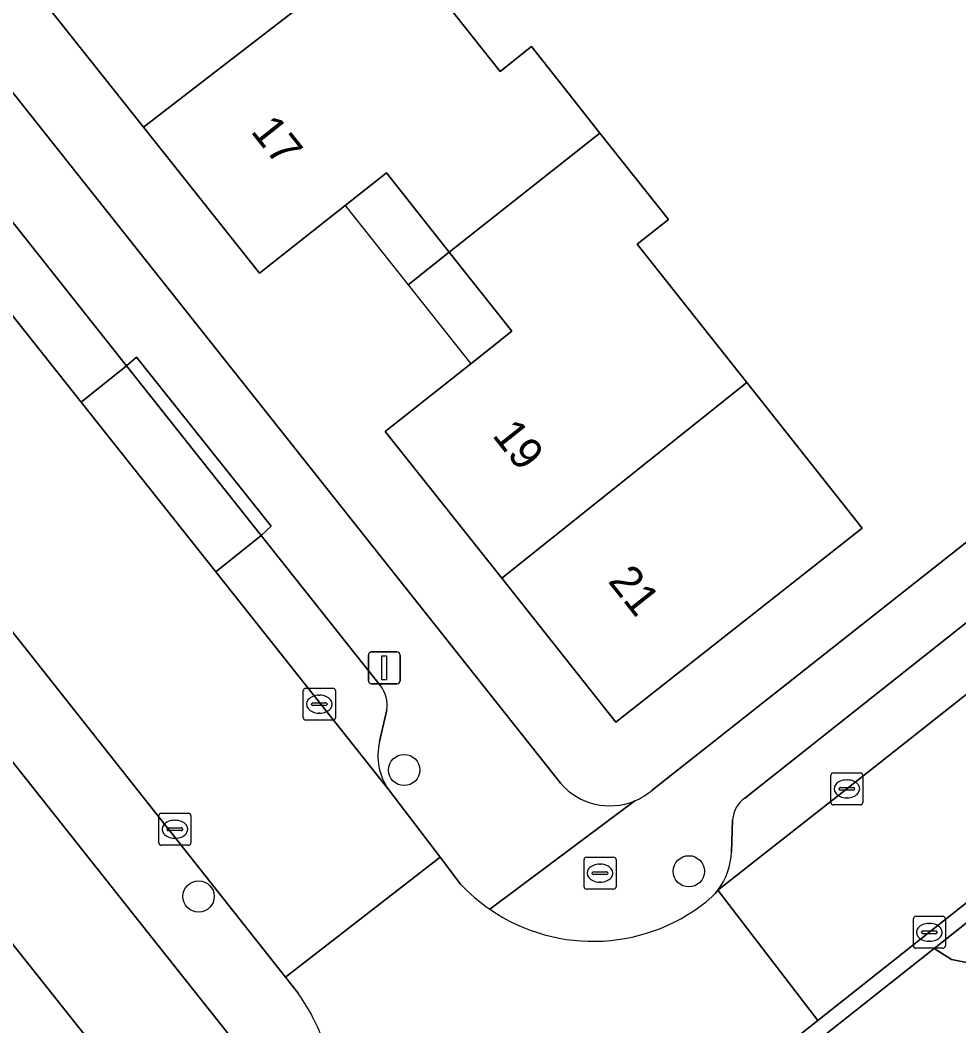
# Model space of a CAD drawing. Extents: x 159626 to 160723, y 388173 to 389416.
# Drawn here: x 160154.71 to 160184.07, y 388555.62 to 388587.08 of the extents above; entities that cross this region are included whole.
import ezdxf

# ---------------------------------------------------------------- set-up
doc = ezdxf.new("R2010")
doc.units = 0
for name, color, linetype in [('IMGEO_Boom', 7, 'Continuous'), ('IMGEO_Brandkraan', 7, 'Continuous'), ('IMGEO_Erf', 7, 'Continuous'), ('IMGEO_Groenvoorziening', 7, 'Continuous'), ('IMGEO_Kolk', 7, 'Continuous'), ('IMGEO_Lichtmast', 7, 'Continuous'), ('IMGEO_Muur', 7, 'Continuous'), ('IMGEO_Pand', 7, 'Continuous'), ('IMGEO_Pand_nummerreeks', 7, 'Continuous'), ('IMGEO_Pand_overbouw', 7, 'Continuous'), ('IMGEO_Parkeervlak_open', 7, 'Continuous'), ('IMGEO_Rijbaan_lokaal_open', 7, 'Continuous'), ('IMGEO_Voetpad_halfverhard', 7, 'Continuous'), ('IMGEO_Voetpad_open', 7, 'Continuous')]:
    doc.layers.add(name, color=color, linetype=linetype)

msp = doc.modelspace()

# ---------------------------------------------------------------- linework, layer by layer
at = {"layer": 'IMGEO_Boom'}
for centre in [(160166.722, 388563.624), (160175.626, 388560.456), (160160.295, 388559.671)]:
    msp.add_circle(centre, 0.489, dxfattribs=at)
at = {"layer": 'IMGEO_Brandkraan'}
for p, q in [((160172.347, 388559.972), (160172.347, 388560.824)), ((160172.422, 388560.898), (160173.274, 388560.898)), ((160173.348, 388560.824), (160173.348, 388559.972)), ((160172.606, 388560.392), (160172.606, 388560.404)), ((160172.649, 388560.441), (160173.047, 388560.441)), ((160172.835, 388560.678), (160172.86, 388560.678)), ((160173.09, 388560.404), (160173.09, 388560.392)), ((160173.044, 388560.355), (160172.646, 388560.355)), ((160172.858, 388560.118), (160172.833, 388560.118)), ((160173.274, 388559.898), (160172.422, 388559.898))]:
    msp.add_line(p, q, dxfattribs=at)
for points in [[(160172.347, 388559.972), (160172.347, 388560.824)], [(160172.422, 388560.898), (160173.274, 388560.898)], [(160173.348, 388560.824), (160173.348, 388559.972)], [(160173.274, 388559.898), (160172.422, 388559.898)]]:
    msp.add_lwpolyline(points, dxfattribs=at)
for centre, radius, start, end in [((160172.424, 388560.822), 0.0765, 91.552, 178.448), ((160172.424, 388560.822), 0.0765, 91.552, 178.448), ((160173.272, 388560.822), 0.0765, 1.552, 88.448), ((160173.272, 388560.822), 0.0765, 1.552, 88.448), ((160172.646, 388560.401), 0.0403, 85.8775, 175.7526), ((160172.643, 388560.391), 0.0366, 178.938, 274.7102), ((160173.047, 388560.398), 0.043, 264.8664, 352.4533), ((160173.051, 388560.403), 0.0386, 1.7309, 96.639), ((160172.424, 388559.974), 0.0765, 181.552, 268.448), ((160172.424, 388559.974), 0.0765, 181.552, 268.448), ((160173.272, 388559.974), 0.0765, 271.552, 358.448), ((160173.272, 388559.974), 0.0765, 271.552, 358.448)]:
    msp.add_arc(centre, radius, start, end, dxfattribs=at)
for centre, major_axis, ratio, start_param, end_param in [((160172.834, 388560.398), (-0.387, 0.002), 0.722429, 4.712389, 7.853982), ((160172.859, 388560.398), (-0.39, 0.002), 0.717154, 1.570796, 4.712389)]:
    msp.add_ellipse(centre, major_axis=major_axis, ratio=ratio, start_param=start_param, end_param=end_param, dxfattribs=at)
at = {"layer": 'IMGEO_Erf'}
for points in [[(160135.461, 388608.789), (160171.618, 388563.205)], [(160166.344, 388589.738), (160169.723, 388585.473), (160170.703, 388586.25), (160171.884, 388584.76), (160172.846, 388583.546), (160174.989, 388580.841), (160174.009, 388580.065), (160177.437, 388575.739), (160181.04, 388571.192), (160173.345, 388565.125), (160169.775, 388569.625), (160166.133, 388574.215), (160168.803, 388576.33), (160170.09, 388577.349), (160168.135, 388579.818), (160166.17, 388582.299), (160164.883, 388581.28), (160162.203, 388579.158), (160158.576, 388583.727), (160154.932, 388588.317)], [(160174.477, 388562.996), (160194.791, 388579.03)], [(160161.479, 388555.046), (160158.23, 388559.144), (160145.158, 388575.629), (160140.484, 388571.932), (160144.027, 388567.471), (160141.577, 388565.524), (160139.117, 388563.569), (160135.574, 388568.03), (160132.045, 388565.227), (160135.588, 388560.766), (160133.044, 388558.742), (160130.663, 388556.847), (160127.12, 388561.308), (160123.577, 388558.488), (160126.051, 388555.373), (160123.516, 388553.364)], [(160142.84, 388555.036), (160147.124, 388558.426), (160144.954, 388561.152), (160149.334, 388564.64), (160151.515, 388561.9), (160157.201, 388554.76)]]:
    msp.add_lwpolyline(points, dxfattribs=at)
for centre, radius, start, end in [((160173.152, 388564.528), 2.025, 220.7845, 292.6627), ((160173.148, 388564.536), 2.034, 292.6696, 310.7914)]:
    msp.add_arc(centre, radius, start, end, dxfattribs=at)
at = {"layer": 'IMGEO_Groenvoorziening'}
msp.add_lwpolyline([(160195.543, 388560.776), (160193.915, 388562.136), (160189.868, 388559.598), (160186.798, 388560.817), (160183.291, 388558.044), (160183.837, 388557.696), (160184.472, 388557.569), (160189.96, 388557.028)], dxfattribs=at)
at = {"layer": 'IMGEO_Kolk'}
for p, q in [((160163.57, 388565.257), (160163.57, 388566.109)), ((160163.645, 388566.183), (160164.497, 388566.183)), ((160164.571, 388566.109), (160164.571, 388565.257)), ((160163.872, 388565.726), (160164.27, 388565.726)), ((160164.058, 388565.963), (160164.083, 388565.963)), ((160163.829, 388565.677), (160163.829, 388565.689)), ((160164.267, 388565.64), (160163.869, 388565.64)), ((160164.081, 388565.403), (160164.056, 388565.403)), ((160164.313, 388565.689), (160164.313, 388565.677)), ((160164.497, 388565.183), (160163.645, 388565.183)), ((160180.14, 388563.534), (160180.992, 388563.534)), ((160180.065, 388562.608), (160180.065, 388563.46)), ((160180.553, 388563.314), (160180.578, 388563.314)), ((160181.066, 388563.46), (160181.066, 388562.608)), ((160180.324, 388563.028), (160180.324, 388563.04)), ((160180.762, 388562.991), (160180.364, 388562.991)), ((160180.367, 388563.077), (160180.765, 388563.077)), ((160180.808, 388563.04), (160180.808, 388563.028)), ((160180.576, 388562.754), (160180.551, 388562.754)), ((160159.129, 388562.271), (160159.981, 388562.271)), ((160180.992, 388562.534), (160180.14, 388562.534)), ((160159.054, 388561.345), (160159.054, 388562.197)), ((160159.542, 388562.051), (160159.567, 388562.051)), ((160160.055, 388562.197), (160160.055, 388561.345)), ((160159.313, 388561.765), (160159.313, 388561.777)), ((160159.751, 388561.728), (160159.353, 388561.728)), ((160159.356, 388561.814), (160159.754, 388561.814)), ((160159.797, 388561.777), (160159.797, 388561.765)), ((160159.565, 388561.491), (160159.54, 388561.491)), ((160159.981, 388561.271), (160159.129, 388561.271)), ((160182.645, 388558.122), (160182.645, 388558.974)), ((160182.72, 388559.048), (160183.572, 388559.048)), ((160183.133, 388558.828), (160183.158, 388558.828)), ((160183.646, 388558.974), (160183.646, 388558.122)), ((160182.904, 388558.542), (160182.904, 388558.554)), ((160183.342, 388558.505), (160182.944, 388558.505)), ((160182.947, 388558.591), (160183.345, 388558.591)), ((160183.388, 388558.554), (160183.388, 388558.542)), ((160183.156, 388558.268), (160183.131, 388558.268)), ((160183.572, 388558.048), (160182.72, 388558.048))]:
    msp.add_line(p, q, dxfattribs=at)
for points in [[(160163.57, 388565.257), (160163.57, 388566.109)], [(160163.645, 388566.183), (160164.497, 388566.183)], [(160164.571, 388566.109), (160164.571, 388565.257)], [(160164.497, 388565.183), (160163.645, 388565.183)], [(160180.14, 388563.534), (160180.992, 388563.534)], [(160180.065, 388562.608), (160180.065, 388563.46)], [(160181.066, 388563.46), (160181.066, 388562.608)], [(160159.129, 388562.271), (160159.981, 388562.271)], [(160180.992, 388562.534), (160180.14, 388562.534)], [(160159.054, 388561.345), (160159.054, 388562.197)], [(160160.055, 388562.197), (160160.055, 388561.345)], [(160159.981, 388561.271), (160159.129, 388561.271)], [(160182.645, 388558.122), (160182.645, 388558.974)], [(160182.72, 388559.048), (160183.572, 388559.048)], [(160183.646, 388558.974), (160183.646, 388558.122)], [(160183.572, 388558.048), (160182.72, 388558.048)]]:
    msp.add_lwpolyline(points, dxfattribs=at)
for centre, radius, start, end in [((160163.647, 388566.107), 0.0765, 91.552, 178.448), ((160163.647, 388566.107), 0.0765, 91.552, 178.448), ((160164.495, 388566.107), 0.0765, 1.552, 88.448), ((160164.495, 388566.107), 0.0765, 1.552, 88.448), ((160163.869, 388565.686), 0.0403, 85.8775, 175.7526), ((160164.274, 388565.688), 0.0386, 1.7309, 96.639), ((160163.866, 388565.676), 0.0366, 178.938, 274.7102), ((160164.27, 388565.683), 0.043, 264.8664, 352.4533), ((160163.647, 388565.259), 0.0765, 181.552, 268.448), ((160163.647, 388565.259), 0.0765, 181.552, 268.448), ((160164.495, 388565.259), 0.0765, 271.552, 358.448), ((160164.495, 388565.259), 0.0765, 271.552, 358.448), ((160180.142, 388563.458), 0.0765, 91.552, 178.448), ((160180.142, 388563.458), 0.0765, 91.552, 178.448), ((160180.99, 388563.458), 0.0765, 1.552, 88.448), ((160180.99, 388563.458), 0.0765, 1.552, 88.448), ((160180.364, 388563.037), 0.0403, 85.8775, 175.7526), ((160180.361, 388563.027), 0.0366, 178.938, 274.7102), ((160180.765, 388563.034), 0.043, 264.8664, 352.4533), ((160180.769, 388563.039), 0.0386, 1.7309, 96.639), ((160180.142, 388562.61), 0.0765, 181.552, 268.448), ((160180.142, 388562.61), 0.0765, 181.552, 268.448), ((160180.99, 388562.61), 0.0765, 271.552, 358.448), ((160180.99, 388562.61), 0.0765, 271.552, 358.448), ((160159.131, 388562.195), 0.0765, 91.552, 178.448), ((160159.131, 388562.195), 0.0765, 91.552, 178.448), ((160159.979, 388562.195), 0.0765, 1.552, 88.448), ((160159.979, 388562.195), 0.0765, 1.552, 88.448), ((160159.353, 388561.774), 0.0403, 85.8775, 175.7526), ((160159.35, 388561.764), 0.0366, 178.938, 274.7102), ((160159.754, 388561.771), 0.043, 264.8664, 352.4533), ((160159.758, 388561.776), 0.0386, 1.7309, 96.639), ((160159.131, 388561.347), 0.0765, 181.552, 268.448), ((160159.131, 388561.347), 0.0765, 181.552, 268.448), ((160159.979, 388561.347), 0.0765, 271.552, 358.448), ((160159.979, 388561.347), 0.0765, 271.552, 358.448), ((160182.722, 388558.972), 0.0765, 91.552, 178.448), ((160182.722, 388558.972), 0.0765, 91.552, 178.448), ((160183.57, 388558.972), 0.0765, 1.552, 88.448), ((160183.57, 388558.972), 0.0765, 1.552, 88.448), ((160182.944, 388558.551), 0.0403, 85.8775, 175.7526), ((160182.941, 388558.541), 0.0366, 178.938, 274.7102), ((160183.345, 388558.548), 0.043, 264.8664, 352.4533), ((160183.349, 388558.553), 0.0386, 1.7309, 96.639), ((160182.722, 388558.124), 0.0765, 181.552, 268.448), ((160182.722, 388558.124), 0.0765, 181.552, 268.448), ((160183.57, 388558.124), 0.0765, 271.552, 358.448), ((160183.57, 388558.124), 0.0765, 271.552, 358.448)]:
    msp.add_arc(centre, radius, start, end, dxfattribs=at)
for centre, major_axis, ratio, start_param, end_param in [((160164.057, 388565.683), (-0.387, 0.002), 0.722429, 4.712389, 7.853982), ((160164.082, 388565.683), (-0.39, 0.002), 0.717154, 1.570796, 4.712389), ((160180.552, 388563.034), (-0.387, 0.002), 0.722429, 4.712389, 7.853982), ((160180.577, 388563.034), (-0.39, 0.002), 0.717154, 1.570796, 4.712389), ((160159.541, 388561.771), (-0.387, 0.002), 0.722429, 4.712389, 7.853982), ((160159.566, 388561.771), (-0.39, 0.002), 0.717154, 1.570796, 4.712389), ((160183.132, 388558.548), (-0.387, 0.002), 0.722429, 4.712389, 7.853982), ((160183.157, 388558.548), (-0.39, 0.002), 0.717154, 1.570796, 4.712389)]:
    msp.add_ellipse(centre, major_axis=major_axis, ratio=ratio, start_param=start_param, end_param=end_param, dxfattribs=at)
at = {"layer": 'IMGEO_Lichtmast'}
for p, q in [((160165.705, 388567.317), (160166.495, 388567.317)), ((160166.495, 388567.317), (160165.705, 388567.317)), ((160165.605, 388566.417), (160165.605, 388567.217)), ((160165.605, 388567.217), (160165.605, 388566.417)), ((160166.595, 388567.217), (160166.595, 388566.417)), ((160166.595, 388566.417), (160166.595, 388567.217)), ((160166.495, 388566.317), (160165.705, 388566.317)), ((160165.705, 388566.317), (160166.495, 388566.317))]:
    msp.add_line(p, q, dxfattribs=at)
msp.add_lwpolyline([(160166.025, 388567.192), (160166.175, 388567.192), (160166.175, 388566.442), (160166.025, 388566.442), (160166.025, 388567.192)], dxfattribs=at)
for centre, start, end in [((160165.705, 388567.217), 90, 180), ((160165.705, 388567.217), 90, 180), ((160166.495, 388567.217), 0, 90), ((160166.495, 388567.217), 360, 90), ((160165.705, 388566.417), 180, 270), ((160165.705, 388566.417), 180, 270), ((160166.495, 388566.417), 270, 0), ((160166.495, 388566.417), 270, 0)]:
    msp.add_arc(centre, 0.1, start, end, dxfattribs=at)
at = {"layer": 'IMGEO_Muur'}
msp.add_lwpolyline([(160145.158, 388575.629), (160158.23, 388559.144)], dxfattribs=at)
at = {"layer": 'IMGEO_Pand'}
for points in [[(160162.835, 388594.166), (160163.814, 388594.942), (160161.671, 388597.646), (160156.949, 388593.934), (160158.906, 388591.456), (160157.718, 388590.518), (160154.932, 388588.317), (160158.576, 388583.727), (160166.344, 388589.738)], [(160172.846, 388583.546), (160171.884, 388584.76), (160170.703, 388586.25), (160169.723, 388585.473), (160166.344, 388589.738), (160158.576, 388583.727), (160162.203, 388579.158), (160164.883, 388581.28), (160166.17, 388582.299), (160168.135, 388579.818)], [(160174.009, 388580.065), (160174.989, 388580.841), (160172.846, 388583.546), (160168.135, 388579.818), (160170.09, 388577.349), (160168.803, 388576.33), (160166.133, 388574.215), (160169.775, 388569.625), (160177.437, 388575.739)], [(160169.775, 388569.625), (160173.345, 388565.125), (160181.04, 388571.192), (160177.437, 388575.739)], [(160154.194, 388549.38), (160156.162, 388550.941), (160154.702, 388552.783), (160157.201, 388554.76), (160151.515, 388561.9), (160149.334, 388564.64), (160144.954, 388561.152), (160147.124, 388558.426)]]:
    msp.add_lwpolyline(points, close=True, dxfattribs=at)
at = {"layer": 'IMGEO_Pand_overbouw'}
for points in [[(160166.847, 388578.8), (160168.135, 388579.818), (160166.17, 388582.299), (160164.883, 388581.28)], [(160168.135, 388579.818), (160166.847, 388578.8), (160168.803, 388576.33), (160170.09, 388577.349)]]:
    msp.add_lwpolyline(points, close=True, dxfattribs=at)
at = {"layer": 'IMGEO_Parkeervlak_open'}
for points in [[(160151.191, 388584.893), (160149.779, 388583.752), (160156.62, 388575.131), (160158.042, 388576.26)], [(160158.042, 388576.26), (160156.62, 388575.131), (160160.83, 388569.826), (160162.254, 388570.957)]]:
    msp.add_lwpolyline(points, close=True, dxfattribs=at)
for points in [[(160194.173, 388573.792), (160193.078, 388575.178), (160177.374, 388562.748)], [(160176.533, 388559.866), (160180.564, 388563.031), (160194.173, 388573.792)], [(160162.254, 388570.957), (160160.83, 388569.826), (160166.241, 388563.007)], [(160165.988, 388566.254), (160162.254, 388570.957)], [(160165.955, 388564.511), (160166.183, 388565.508)], [(160176.992, 388562.069), (160176.959, 388561.059)]]:
    msp.add_lwpolyline(points, dxfattribs=at)
for centre, radius, start, end in [((160165.162, 388565.64), 1.029, 352.6466, 36.6514), ((160167.762, 388564.075), 1.859, 166.4472, 215.0863), ((160177.913, 388561.998), 0.923, 125.6816, 175.5949), ((160174.837, 388561.144), 2.124, 323.001, 357.6975)]:
    msp.add_arc(centre, radius, start, end, dxfattribs=at)
at = {"layer": 'IMGEO_Rijbaan_lokaal_open'}
for points in [[(160149.779, 388583.752), (160145.555, 388589.075), (160131.633, 388606.617), (160126.765, 388602.964), (160131.369, 388597.145), (160133.698, 388594.201), (160140.687, 388585.366), (160143.016, 388582.42), (160143.389, 388581.95), (160147.05, 388577.322), (160163.008, 388557.148), (160167.849, 388560.894), (160166.241, 388563.007), (160160.83, 388569.826), (160156.62, 388575.131)], [(160208.991, 388579.024), (160207.952, 388584.939), (160197.138, 388576.144), (160194.173, 388573.792), (160180.564, 388563.031), (160176.533, 388559.866), (160179.663, 388555.791)]]:
    msp.add_lwpolyline(points, close=True, dxfattribs=at)
for points in [[(160168.485, 388560.059), (160167.849, 388560.894), (160163.008, 388557.148), (160163.409, 388556.641)], [(160162.783, 388548.914), (160162.571, 388548.746), (160162.406, 388548.616), (160165.735, 388544.757), (160179.663, 388555.791), (160176.533, 388559.866)], [(160176.533, 388559.866), (160176.446, 388559.765), (160176.349, 388559.653)]]:
    msp.add_lwpolyline(points, dxfattribs=at)
for centre, radius, start, end in [((160172.684, 388564.01), 5.766, 223.2569, 235.3147), ((160172.628, 388563.949), 5.683, 235.4289, 310.8997), ((160158.059, 388552.868), 6.547, 21.8515, 35.189)]:
    msp.add_arc(centre, radius, start, end, dxfattribs=at)
at = {"layer": 'IMGEO_Voetpad_halfverhard'}
msp.add_lwpolyline([(160189.96, 388557.028), (160184.472, 388557.569), (160183.837, 388557.696), (160183.291, 388558.044), (160163.165, 388542.123), (160163.359, 388540.836), (160162.792, 388535.315)], dxfattribs=at)
at = {"layer": 'IMGEO_Voetpad_open'}
for points in [[(160171.618, 388563.205), (160135.461, 388608.789), (160134.05, 388606.484), (160137.783, 388601.782), (160138.132, 388602.046), (160140.466, 388599.11), (160140.135, 388598.819), (160146.976, 388590.202), (160147.342, 388590.465), (160151.524, 388585.162), (160151.191, 388584.893), (160158.042, 388576.26), (160158.356, 388576.538), (160162.569, 388571.246), (160162.254, 388570.957), (160165.988, 388566.254)], [(160215.64, 388589.463), (160211.827, 388590.336), (160208.842, 388589.812), (160208.079, 388589.559), (160194.791, 388579.03), (160174.477, 388562.996)], [(160177.374, 388562.748), (160193.078, 388575.178), (160192.82, 388575.516), (160195.763, 388577.846), (160196.044, 388577.526), (160205.44, 388584.996)], [(160129.272, 388515.256), (160132.407, 388517.741), (160159.791, 388539.449), (160163.165, 388542.123), (160183.291, 388558.044), (160186.798, 388560.817), (160209.905, 388579.089), (160210.744, 388579.616)], [(160208.991, 388579.024), (160179.663, 388555.791), (160165.735, 388544.757), (160162.49, 388542.187), (160128.633, 388515.322)], [(160147.05, 388577.322), (160146.412, 388576.752), (160145.158, 388575.629), (160158.23, 388559.144), (160161.479, 388555.046)], [(160163.409, 388556.641), (160163.008, 388557.148), (160147.05, 388577.322)], [(160166.183, 388565.508), (160165.955, 388564.511)], [(160166.241, 388563.007), (160167.849, 388560.894), (160168.485, 388560.059)], [(160173.932, 388562.659), (160169.403, 388559.269)], [(160169.403, 388559.269), (160173.932, 388562.659)], [(160176.959, 388561.059), (160176.992, 388562.069)], [(160176.349, 388559.653), (160176.446, 388559.765), (160176.533, 388559.866)]]:
    msp.add_lwpolyline(points, dxfattribs=at)
msp.add_lwpolyline([(160158.042, 388576.26), (160162.254, 388570.957), (160162.569, 388571.246), (160158.356, 388576.538)], close=True, dxfattribs=at)
for centre, radius, start, end in [((160165.162, 388565.64), 1.029, 352.6466, 36.6514), ((160167.762, 388564.075), 1.859, 166.4472, 215.0863), ((160173.152, 388564.528), 2.025, 220.7845, 292.6627), ((160173.148, 388564.536), 2.034, 292.6696, 310.7914), ((160177.913, 388561.998), 0.923, 125.6816, 175.5949), ((160174.837, 388561.144), 2.124, 323.001, 357.6975), ((160172.684, 388564.01), 5.766, 223.2569, 235.3147), ((160172.628, 388563.949), 5.683, 235.4289, 310.8997), ((160158.059, 388552.868), 6.547, 21.8515, 35.189)]:
    msp.add_arc(centre, radius, start, end, dxfattribs=at)

# ---------------------------------------------------------------- texts
at = {"layer": 'IMGEO_Pand_nummerreeks'}
for s, rotation, p in [('17', 308.4453, (160161.902, 388583.591)), ('19', 308.4281, (160169.453, 388574.085)), ('21', 308.4285, (160173.073, 388569.523))]:
    msp.add_text(s, height=1, rotation=rotation, dxfattribs=at).set_placement(p)

doc.saveas('drawing.dxf')
